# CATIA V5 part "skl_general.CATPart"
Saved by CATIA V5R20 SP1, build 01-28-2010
Part number: skl_general
Publications: "epaisseur_bielle", "CB", "AD", "CA", "BD", "AE", "EF", "Plan.1", "Plan.2", "C", "A", "B", "D", "E", "G", "F"
Bounding box of the stored display mesh (mm): x -20.434 to 29.779, y 0 to 0, z 0 to 82.679
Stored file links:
  C:\Users\Matthieu\Desktop\IAO_2012_mcamard_Catia\skl_general.CATPart
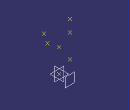
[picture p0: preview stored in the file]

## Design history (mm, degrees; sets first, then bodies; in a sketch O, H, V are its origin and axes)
Parameters
  epaisseur_bielle = 20 mm
  CB = 25 mm
  AD = 25 mm {= CB}
  CA = 45 mm
  BD = 45 mm {= CA}
  AE = 30 mm
  EF = 20 mm
Set1
  Plane1: type Offset, RefPlane zx-plane, Offset 0
  Plane2: type Offset, RefPlane Plane1, Offset 20 {= epaisseur_bielle}
  Point1 "C": type OnPlane, Support Plane1, H 0, V 0, Direction (-1, 0, 0)
  Point2 "A": type OnPlane, Support zx-plane, H 0, V 45 {= CA}, Direction (-1, 0, 0)
  Circle1: type CtrRad, Start 0, End 180, Center Point1, Support Plane1, Radius 25, FirstDirection (-1, 0, 0)
  Point3 "B": type OnCurve, Support Circle1, RefPoint {extremum Reference Circle1, Direction (1, 2, 3)}, Length 125.116
  Circle2: type CtrRad, Start 0, End 180, Center Point3, Support Plane1, Radius 45, FirstDirection (-1, 0, 0)
  Circle3: type CtrRad, Start 0, End 180, Center Point2, Support Plane1, Radius 25 {= AD}, FirstDirection (-1, 0, 0)
  Intersect1: ToIntersect1 Circle2, ToIntersect2 Circle3
  Extract1: ExtractElem vertex of Intersect1
  Point4 "D": (0, 0, 0), relative to Extract1
  Circle4: type CtrRad, Start 0, End 180, Center Point2, Support Plane1, Radius 30 {= AE}, FirstDirection (-1, 0, 0)
  Point5 "E": type OnCurve, Support Circle4, RefPoint {extremum Reference Circle4, Direction (1, 2, 3)}, Length 17.275
  Circle5: type CtrRad, Start 0, End 180, Center Point5, Support Plane1, Radius 20 {= EF}, FirstDirection (-1, 0, 0)
  Point6 "F": type OnCurve, Support Circle5, RefPoint {extremum Reference Circle5, Direction (1, 2, 3)}, Length 0
  Line1: type PtPt, FirstPoint Point3, SecondPoint Point4
  Line2: type Angle, RefPoint Point6, Curve Line1, Start 0, End 20, Angle 90
  Intersect2: ToIntersect1 Line1, ToIntersect2 Line2
  Point7 "G": (0, 0, 0), relative to Intersect2
Body1 (main body)
Relations
  Circle3.Radius = CA AD (deactivated)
